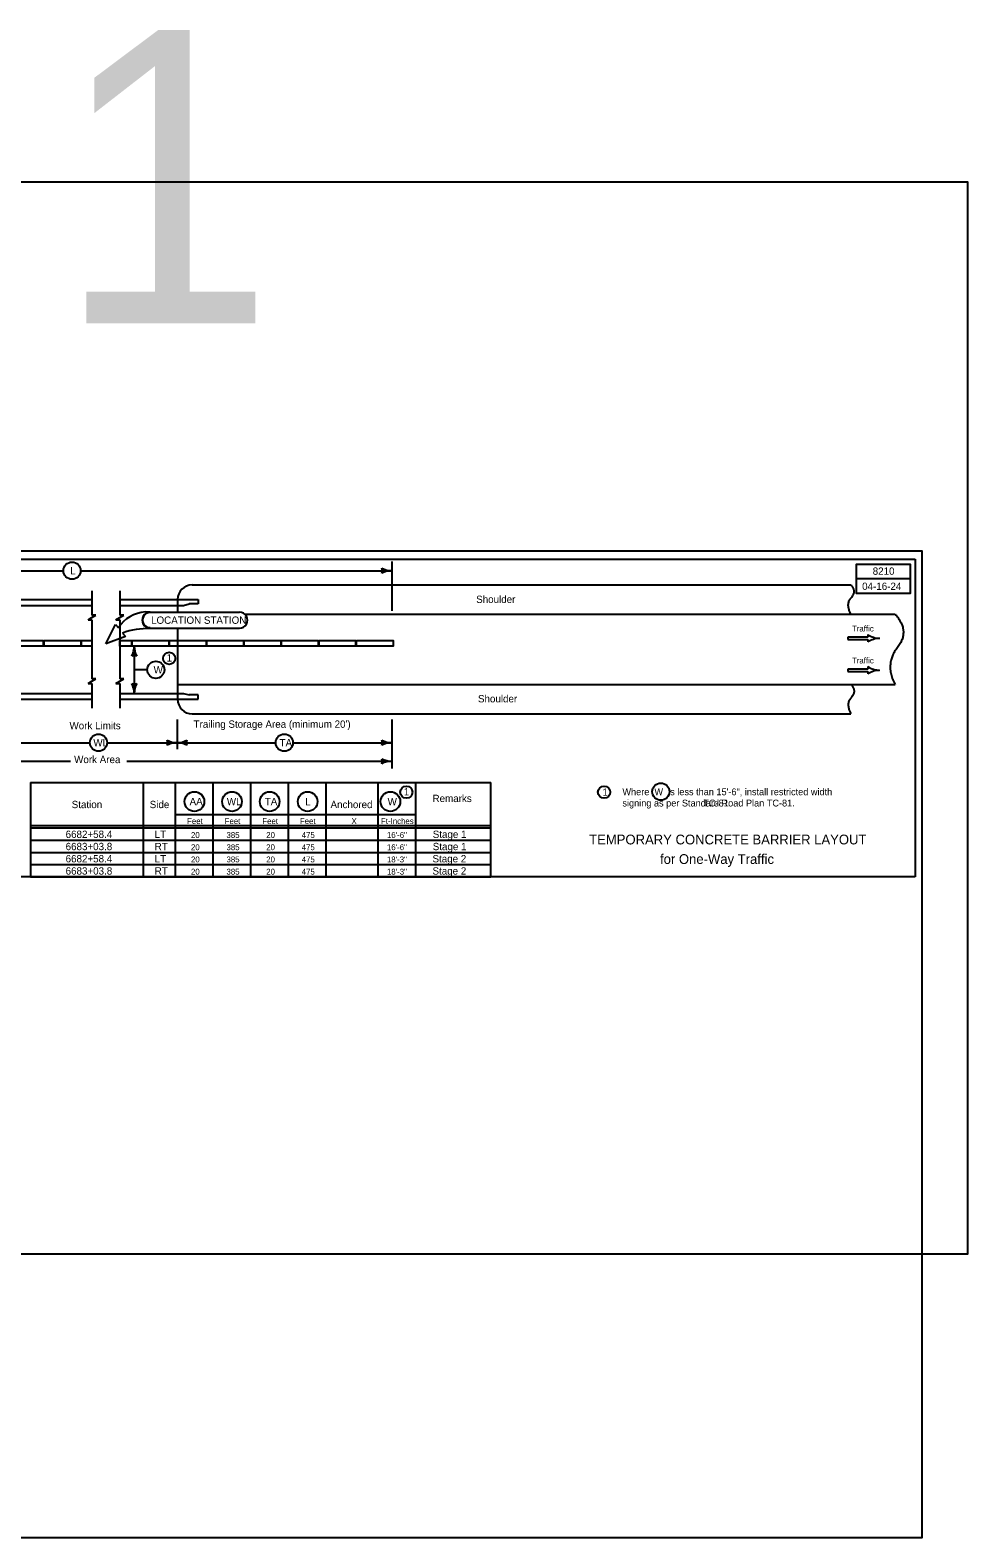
# Model space of a CAD drawing. Extents: x 10041 to 81668, y 7924 to 11018.
# Drawn here: x 11442 to 13362, y 7924 to 11009 of the extents above; entities that cross this region are included whole.
import ezdxf

# ---------------------------------------------------------------- set-up
doc = ezdxf.new("R2010")
doc.units = 0
for name, color, linetype in [('dsnCellElements', 7, 'Continuous'), ('dsnStdNameDate', 7, 'Continuous'), ('Level 1', 7, 'Continuous'), ('Level 10', 7, 'Continuous'), ('Level 12', 7, 'Continuous'), ('Level 4', 7, 'Continuous'), ('Level 5', 7, 'Continuous'), ('Level 6', 7, 'Continuous'), ('Level 63', 7, 'Continuous'), ('SheetAddendum', 7, 'Continuous'), ('SheetBorder', 7, 'Continuous'), ('SheetText', 7, 'Continuous')]:
    doc.layers.add(name, color=color, linetype=linetype)

msp = doc.modelspace()

# ---------------------------------------------------------------- linework, layer by layer
at = {"layer": 'dsnCellElements'}
msp.add_lwpolyline([(10041.2, 8505), (13362.1, 8505), (13362.1, 10698.4), (10041.2, 10698.4)], close=True, dxfattribs=at)
at = {"layer": 'Level 1'}
for p, q in [((12182.6, 9921.7), (12182.6, 9820.9)), ((10632, 9903.1), (11510.6, 9903.1)), ((11545.9, 9903.1), (12182.6, 9903.1)), ((11774.3, 9874.1), (13122.7, 9874.1)), ((11422.9, 9844.1), (11568.9, 9844.1)), ((11568.9, 9862.1), (11568.9, 9812.3)), ((11626, 9862.1), (11626, 9812.3)), ((11626, 9844.1), (11744.3, 9844.1)), ((11744.3, 9844.1), (11786.3, 9844.1)), ((11744.3, 9844.1), (11744.3, 9818.1)), ((11786.3, 9844.1), (11786.3, 9835.1)), ((11422.9, 9832.1), (11568.9, 9832.1)), ((11568.9, 9807.2), (11576.9, 9812.3)), ((11576.9, 9812.3), (11568.9, 9812.3)), ((11618, 9802.2), (11634, 9812.3)), ((11626, 9832.1), (11744.3, 9832.1)), ((11634, 9812.3), (11626, 9812.3)), ((11678.4, 9818.7), (11687.9, 9819)), ((11687.9, 9819), (11687.9, 9817.2)), ((11687.9, 9818.1), (11871, 9818.1)), ((11744.3, 9832.1), (11756.3, 9832.1)), ((11756.3, 9832.1), (11768.3, 9835.1)), ((11786.3, 9835.1), (11768.3, 9835.1)), ((11881.8, 9814.1), (13213.1, 9814.1)), ((11560.9, 9802.2), (11568.9, 9807.2)), ((11560.9, 9802.2), (11568.9, 9802.2)), ((11568.9, 9802.2), (11568.9, 9742.1)), ((11597.4, 9753.1), (11617.5, 9793.1)), ((11617.5, 9793.1), (11623.2, 9786.1)), ((11618, 9802.2), (11626, 9802.2)), ((11626, 9802.2), (11626, 9742.1)), ((11687.9, 9786.5), (11687.9, 9784.7)), ((11687.9, 9785.6), (11871, 9785.6)), ((11744.3, 9785.6), (11744.3, 9640.1)), ((11637.6, 9768.1), (11597.4, 9753.1)), ((11631.7, 9775.5), (11637.6, 9768.1)), ((13157.4, 9767), (13116.2, 9767)), ((13116.2, 9767), (13116.2, 9762.5)), ((13116.2, 9762.5), (13157.4, 9762.5)), ((13157.4, 9772.2), (13157.4, 9767)), ((13157.4, 9762.5), (13157.4, 9757.2)), ((13181.3, 9764.7), (13181.3, 9764.7)), ((11568.9, 9742.1), (11568.9, 9682.1)), ((11626, 9742.1), (11626, 9682.1)), ((11655.6, 9748.4), (11655.6, 9652.1)), ((11682.2, 9700.3), (11655.6, 9700.3)), ((13157.4, 9701.5), (13116.2, 9701.5)), ((13116.2, 9701.5), (13116.2, 9697)), ((13116.2, 9697), (13157.4, 9697)), ((13157.4, 9706.8), (13157.4, 9701.5)), ((13157.4, 9697), (13157.4, 9691.8)), ((13181.3, 9699.3), (13181.3, 9699.3)), ((11560.9, 9672), (11568.9, 9677)), ((11560.9, 9672), (11568.9, 9672)), ((11568.9, 9677), (11576.9, 9682.1)), ((11576.9, 9682.1), (11568.9, 9682.1)), ((11568.9, 9672), (11568.9, 9622.1)), ((11618, 9672), (11634, 9682.1)), ((11618, 9672), (11626, 9672)), ((11634, 9682.1), (11626, 9682.1)), ((11626, 9672), (11626, 9622.1)), ((11744.3, 9670.1), (13213.1, 9670.1)), ((11422.9, 9652.1), (11568.9, 9652.1)), ((11422.9, 9640.1), (11568.9, 9640.1)), ((11626, 9652.1), (11744.3, 9652.1)), ((11626, 9640.1), (11744.3, 9640.1)), ((11744.3, 9652.1), (11756.3, 9652.1)), ((11744.3, 9640.1), (11786.3, 9640.1)), ((11756.3, 9652.1), (11768.3, 9649.1)), ((11786.3, 9649.1), (11768.3, 9649.1)), ((11786.3, 9640.1), (11786.3, 9649.1)), ((11743.1, 9598.9), (11743.1, 9537.6)), ((11774.3, 9610.1), (13122.7, 9610.1)), ((12182.6, 9598.9), (12182.6, 9498)), ((11421.7, 9551.1), (11564.9, 9551.1)), ((11599.9, 9551.1), (11743.1, 9551.1)), ((11612.6, 9551.1), (11743.1, 9551.1)), ((11743.1, 9551.1), (11945.2, 9551.1)), ((11980.5, 9551.1), (12182.6, 9551.1)), ((10934.2, 9513.2), (11525, 9513.2)), ((11640.3, 9513.2), (12182.6, 9513.2)), ((11641.6, 9513.2), (11743.1, 9513.2)), ((11674.2, 9276.7), (11674.2, 9469.7)), ((11740.2, 9276.7), (11740.2, 9469.7)), ((11817.2, 9276.7), (11817.2, 9469.7)), ((11894.2, 9276.7), (11894.2, 9469.7)), ((11971.2, 9276.7), (11971.2, 9469.7)), ((11443.2, 9381.7), (12385.7, 9381.7)), ((11740.2, 9403.9), (12231.7, 9403.9)), ((11443.2, 9376.7), (12385.7, 9376.7))]:
    msp.add_line(p, q, dxfattribs=at)
for points in [[(11394.4, 9760.4), (11469.4, 9760.4), (11469.4, 9748.4), (11394.4, 9748.4)], [(11470.9, 9760.4), (11545.9, 9760.4), (11545.9, 9748.4), (11470.9, 9748.4)], [(11651.3, 9760.4), (11726.3, 9760.4), (11726.3, 9748.4), (11651.3, 9748.4)], [(11727.8, 9760.4), (11802.8, 9760.4), (11802.8, 9748.4), (11727.8, 9748.4)], [(11804.3, 9760.4), (11879.3, 9760.4), (11879.3, 9748.4), (11804.3, 9748.4)], [(11880.8, 9760.4), (11955.8, 9760.4), (11955.8, 9748.4), (11880.8, 9748.4)], [(11957.3, 9760.4), (12032.3, 9760.4), (12032.3, 9748.4), (11957.3, 9748.4)], [(12033.8, 9760.4), (12108.8, 9760.4), (12108.8, 9748.4), (12033.8, 9748.4)], [(12110.3, 9760.4), (12185.3, 9760.4), (12185.3, 9748.4), (12110.3, 9748.4)]]:
    msp.add_lwpolyline(points, close=True, dxfattribs=at)
for points in [[(11568.9, 9748.4), (11547.4, 9748.4), (11547.4, 9760.4), (11568.9, 9760.4)], [(11568.9, 9760.4), (11568.9, 9748.4)], [(11626, 9748.4), (11626, 9760.4)], [(11626, 9760.4), (11649.8, 9760.4), (11649.8, 9748.4), (11626, 9748.4)]]:
    msp.add_lwpolyline(points, dxfattribs=at)
for centre, radius in [((11528.2, 9903.1), 17.6), ((11727, 9723.7), 12.5), ((11699.8, 9700.3), 17.6), ((11582.4, 9551.1), 17.6), ((11962.8, 9551.1), 17.6), ((11778.7, 9430.7), 20.1), ((11855.7, 9430.7), 20.1), ((11932.7, 9430.7), 20.1), ((12010.5, 9430.7), 20.1), ((12179.9, 9430.7), 20.1), ((12212.6, 9449.9), 12.5), ((12617.4, 9449.9), 12.5), ((12733.5, 9451), 17.6)]:
    msp.add_circle(centre, radius, dxfattribs=at)
for centre, radius, start, end in [((12146.9, 9903.1), 16.4, 342.2666, 17.7333), ((12182.6, 9945.6), 42.5, 241.9275, 270), ((11774.3, 9844.1), 30, 90, 180), ((12182.6, 9860.6), 42.5, 90, 118.0725), ((13183.3, 9813), 48.4, 237.618, 267.648), ((13183.3, 9716.4), 48.4, 92.352, 122.382), ((11613.1, 9748.4), 42.5, 331.9275, 0), ((11655.6, 9712.8), 16.4, 72.2666, 107.7334), ((11698.1, 9748.4), 42.5, 180, 208.0725), ((13183.3, 9747.6), 48.4, 237.618, 267.648), ((13183.3, 9651), 48.4, 92.352, 122.382), ((11655.6, 9687.8), 16.4, 252.2666, 287.7334), ((11613.1, 9652.1), 42.5, 0, 28.0725), ((11698.1, 9652.1), 42.5, 151.9275, 180), ((11774.3, 9640.1), 30, 180, 270), ((11707.4, 9551.1), 16.4, 342.2666, 17.7333), ((11743.1, 9593.6), 42.5, 241.9275, 270), ((11743.1, 9508.6), 42.5, 90, 118.0725), ((11743.1, 9593.6), 42.5, 270, 298.0725), ((11743.1, 9508.6), 42.5, 61.9275, 90), ((11778.7, 9551.1), 16.4, 162.2666, 197.7334), ((12146.9, 9551.1), 16.4, 342.2666, 17.7333), ((12182.6, 9593.6), 42.5, 241.9275, 270), ((12182.6, 9508.6), 42.5, 90, 118.0725), ((12146.9, 9513.2), 16.4, 342.2666, 17.7333), ((12182.6, 9555.7), 42.5, 241.9275, 270), ((12182.6, 9470.7), 42.5, 90, 118.0725)]:
    msp.add_arc(centre, radius, start, end, dxfattribs=at)
for centre, major_axis, start_param, end_param in [((11682.9, 9748.4), (-70.8, 0), 4.776871, 5.71778), ((11687.9, 9801.9), (-16.3, 0), 4.712389, 7.853982), ((11687.9, 9801.9), (15.4, 0), 1.570796, 4.712389), ((11871, 9801.9), (16.3, 0), 4.712389, 7.853982), ((11685, 9628.7), (-156.9, 0), 4.694293, 5.059134)]:
    msp.add_ellipse(centre, major_axis=major_axis, ratio=0.995025, start_param=start_param, end_param=end_param, dxfattribs=at)
for points in [[(13122.7, 9874.1), (13134.5, 9860), (13110.9, 9835), (13122.2, 9814.2)], [(13213.1, 9814.1), (13244.5, 9779.7), (13191.1, 9711.7), (13213.1, 9670.1)], [(13123.2, 9670.1), (13135, 9656), (13111.4, 9631), (13122.7, 9610.1)]]:
    msp.add_open_spline(points, degree=2, dxfattribs=at)
at = {"layer": 'Level 10'}
for p, q in [((10149.1, 9926.7), (13254.1, 9926.7)), ((13254.1, 9926.7), (13254.1, 9276.7))]:
    msp.add_line(p, q, dxfattribs=at)
at = {"layer": 'Level 4'}
msp.add_lwpolyline([(13244.1, 9916.7), (13244.1, 9856.7), (13134.1, 9856.7), (13134.1, 9916.7), (13244.1, 9916.7), (13244.1, 9886.7), (13134.1, 9886.7)], dxfattribs=at)
at = {"layer": 'Level 5'}
msp.add_line((13254.1, 9276.7), (10149.1, 9276.7), dxfattribs=at)
at = {"layer": 'Level 63'}
for p, q in [((11443.2, 9469.7), (11443.2, 9276.7)), ((11443.2, 9469.7), (12385.7, 9469.7)), ((12048.2, 9276.7), (12048.2, 9469.7)), ((12154.7, 9276.7), (12154.7, 9469.7)), ((12231.7, 9276.7), (12231.7, 9469.7)), ((12385.7, 9276.7), (12385.7, 9469.7))]:
    msp.add_line(p, q, dxfattribs=at)
at = {"layer": 'SheetAddendum'}
for p, q in [((11443.2, 9351.7), (12385.7, 9351.7)), ((11443.2, 9326.7), (12385.7, 9326.7)), ((11443.2, 9301.7), (12385.7, 9301.7)), ((11443.2, 9276.7), (12385.7, 9276.7))]:
    msp.add_line(p, q, dxfattribs=at)
at = {"layer": 'SheetBorder'}
msp.add_lwpolyline([(10132.5, 9944), (13267.5, 9944), (13267.5, 7924), (10132.5, 7924)], close=True, dxfattribs=at)

# ---------------------------------------------------------------- texts
at = {"layer": 'dsnStdNameDate'}
for s, p in [('8210', (13167.3, 9894.7)), ('04-16-24', (13145.6, 9863.7))]:
    msp.add_text(s, height=15, dxfattribs=at).set_placement(p)
at = {"layer": 'Level 12'}
for s, height, p in [('L', 15, (11524.3, 9895.6)), ('Shoulder', 15, (12355.5, 9837)), ('LOCATION STATION', 15, (11690, 9794.4)), ('Traffic', 12, (13124.9, 9778.7)), ('1', 15, (11721.7, 9717.1)), ('Traffic', 12, (13124.9, 9713.3)), ('W', 15, (11695.2, 9692.8)), ('Shoulder', 15, (12359.2, 9633.6)), ("Trailing Storage Area (minimum 20')", 15, (11777, 9581.6)), ('Work Limits', 15, (11523, 9578.6)), ('WL', 15, (11571.9, 9543.6)), ('TA', 15, (11953, 9543.6)), ('Work Area', 15, (11532.5, 9509.3)), ('1', 15, (12207.4, 9443.3)), ('Remarks', 15, (12266.2, 9429.6)), ('1', 15, (12614, 9442.4)), ('Where  W  is less than 15\'-6", install restricted width', 14, (12654.9, 9443.6)), ('Station', 15, (11527.5, 9417.2)), ('Side', 15, (11687.2, 9417.2)), ('AA', 15, (11768.9, 9423.2)), ('WL', 15, (11845.1, 9423.2)), ('TA', 15, (11922.8, 9423.2)), ('L', 15, (12005.5, 9422.8)), ('Anchored', 15, (12057.4, 9417.2)), ('W', 15, (12174.3, 9422.8)), ('signing as per Standard Road Plan TC-81.', 14, (12654.9, 9420.6)), ('                                TC-81', 14, (12654.2, 9420.6)), ('Feet', 12, (11763.7, 9384.7)), ('Feet', 12, (11840.7, 9384.7)), ('Feet', 12, (11917.7, 9384.7)), ('Feet', 12, (11994.7, 9384.7)), ('X', 12, (12100.3, 9384.7)), ('Ft-Inches', 12, (12160.7, 9384.7)), ('6682+58.4', 15, (11515.1, 9356.2)), ('LT', 15, (11697.4, 9356.2)), ('20', 12, (11771.7, 9356.2)), ('385', 12, (11844.4, 9356.2)), ('20', 12, (11925.7, 9356.2)), ('475', 12, (11998.4, 9356.2)), ('16\'-6"', 12, (12172.8, 9356.2)), ('Stage 1', 15, (12266.6, 9356.2)), ('6682+58.4', 15, (11515.1, 9306.2)), ('6683+03.8', 15, (11515.1, 9331.2)), ('RT', 15, (11697.4, 9331.2)), ('LT', 15, (11697.4, 9306.2)), ('20', 12, (11771.7, 9331.2)), ('20', 12, (11771.7, 9306.2)), ('385', 12, (11844.4, 9331.2)), ('385', 12, (11844.4, 9306.2)), ('20', 12, (11925.7, 9331.2)), ('20', 12, (11925.7, 9306.2)), ('475', 12, (11998.4, 9331.2)), ('475', 12, (11998.4, 9306.2)), ('16\'-6"', 12, (12172.8, 9331.2)), ('18\'-3"', 12, (12172.8, 9306.2)), ('Stage 2', 15, (12266.1, 9306.2)), ('Stage 1', 15, (12266.6, 9331.2)), ('6683+03.8', 15, (11515.1, 9281.2)), ('RT', 15, (11697.4, 9281.2)), ('20', 12, (11771.7, 9281.2)), ('385', 12, (11844.4, 9281.2)), ('20', 12, (11925.7, 9281.2)), ('475', 12, (11998.4, 9281.2)), ('18\'-3"', 12, (12172.8, 9281.2)), ('Stage 2', 15, (12266.1, 9281.2))]:
    msp.add_text(s, height=height, dxfattribs=at).set_placement(p)
at = {"layer": 'Level 6'}
for s, p in [('TEMPORARY CONCRETE BARRIER LAYOUT', (12586.8, 9343)), ('for One-Way Traffic', (12731.9, 9303))]:
    msp.add_text(s, height=20, dxfattribs=at).set_placement(p)
at = {"layer": 'SheetText'}
msp.add_text('1', height=600, dxfattribs=at).set_placement((11496.6, 10409.2))

doc.saveas('drawing.dxf')
